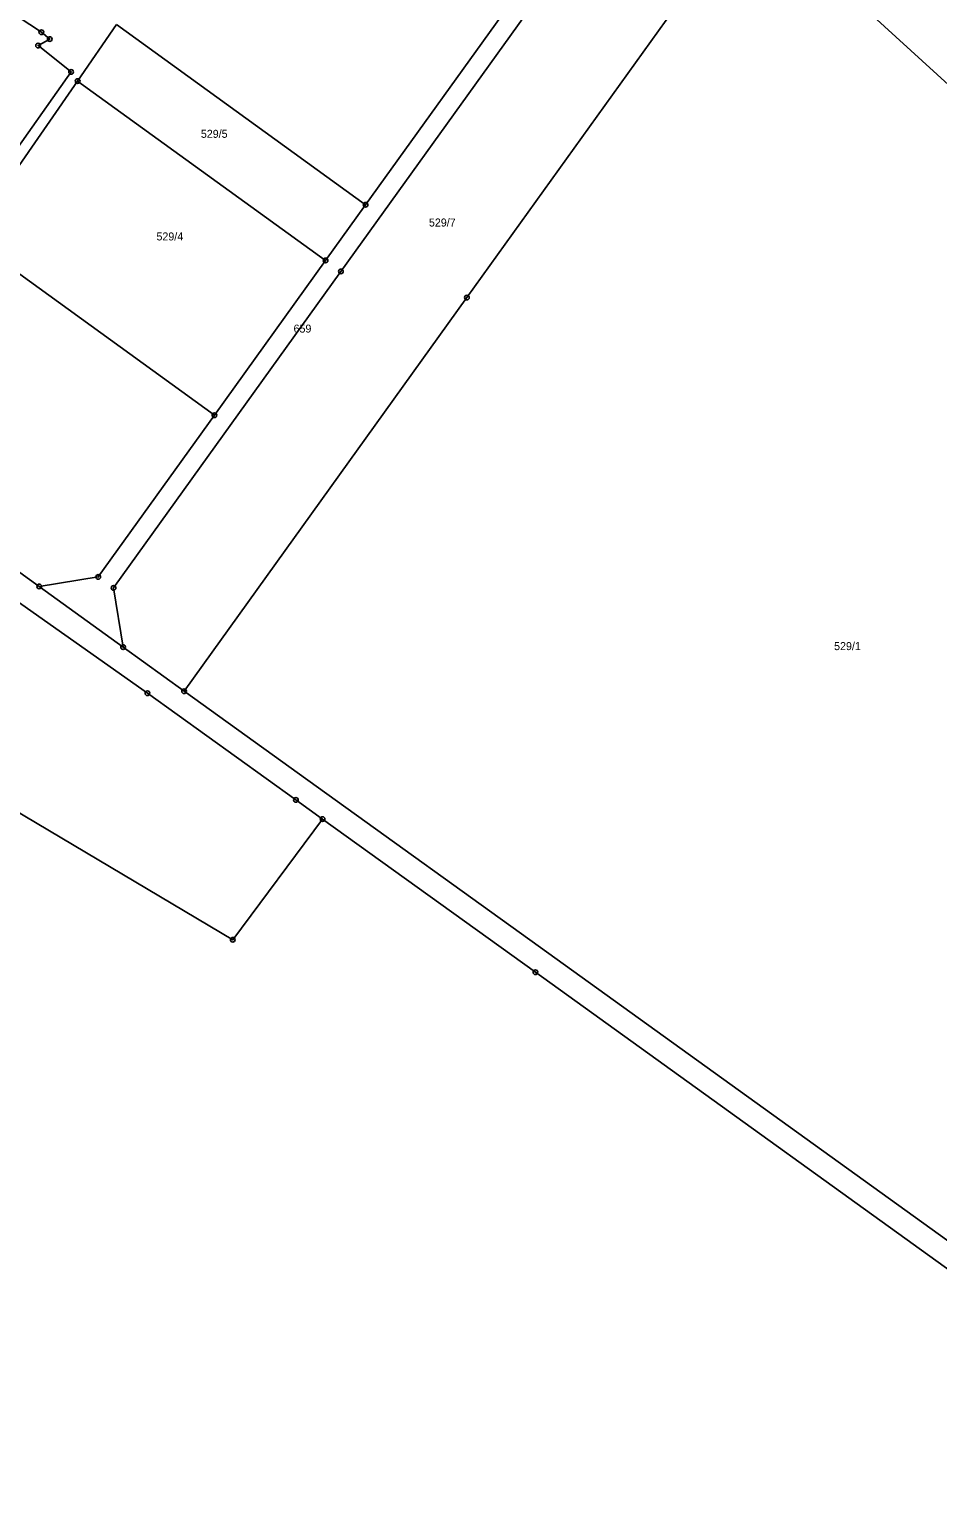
# Model space of a CAD drawing. Extents: x -758582 to -751794, y -998770 to -994350.
# Drawn here: x -753914.4 to -753721.4, y -997454.9 to -997140.7 of the extents above; entities that cross this region are included whole.
import ezdxf

# ---------------------------------------------------------------- set-up
doc = ezdxf.new("R2010")
doc.units = 0
for name, color, linetype in [('Hranice parcel', 7, 'Continuous'), ('Parcelní čísla', 7, 'Continuous'), ('Značky bodu BP', 7, 'Continuous')]:
    doc.layers.add(name, color=color, linetype=linetype)

msp = doc.modelspace()

# ---------------------------------------------------------------- linework, layer by layer
at = {"layer": 'Hranice parcel'}
for p, q in [((-753843, -997177.95), (-753781.75, -997092.75)), ((-753904.22, -997151.68), (-753895.93, -997139.69)), ((-753843, -997177.95), (-753895.93, -997139.69)), ((-753917.91, -997171.47), (-753904.22, -997151.68)), ((-753851.51, -997189.79), (-753904.22, -997151.68)), ((-753851.51, -997189.79), (-753843, -997177.95)), ((-753875.15, -997222.67), (-753927.26, -997184.99)), ((-753875.15, -997222.67), (-753851.51, -997189.79)), ((-753956.46, -997227.2), (-753912.39, -997259.05)), ((-753894.56, -997271.94), (-753912.39, -997259.05)), ((-753894.56, -997271.94), (-753881.59, -997281.3))]:
    msp.add_line(p, q, dxfattribs=at)
for points in [[(-753778.99, -997095.76), (-753848.26, -997192.12), (-753896.59, -997259.35), (-753894.56, -997271.94)], [(-753761.15, -997113.77), (-753821.47, -997197.67), (-753881.59, -997281.3)], [(-753761.15, -997113.77), (-753757.5, -997117.4), (-753719.05, -997152.45), (-753671.74, -997191.64), (-753659.01, -997201.73), (-753633.73, -997223.1), (-753599.82, -997250.03)], [(-753919.98, -997170.14), (-753905.61, -997149.74), (-753912.63, -997144.13), (-753910.16, -997142.77), (-753911.94, -997141.3), (-753916.88, -997138.01), (-753932.01, -997161.86)], [(-753852.15, -997308.47), (-753871.25, -997334.09), (-753918.09, -997306.31), (-753976.45, -997272.88), (-753996.61, -997232.71), (-754036.34, -997178.45)], [(-753912.39, -997259.05), (-753899.84, -997257.02), (-753875.15, -997222.67)], [(-753959.77, -997232.16), (-753889.38, -997281.72), (-753857.82, -997304.4), (-753852.15, -997308.47)], [(-753881.59, -997281.3), (-753855.26, -997300.22), (-753804.06, -997337.03), (-753710.64, -997404.19)], [(-753854.21, -997753.52), (-753840.93, -997729.59), (-753764.33, -997590.99), (-753741.88, -997551.71), (-753721.27, -997514.44), (-753700.33, -997475.68), (-753688.35, -997452.29), (-753682.81, -997440.16), (-753682.49, -997434.57), (-753687.49, -997427.26), (-753699.24, -997418.42), (-753806.91, -997341), (-753852.15, -997308.47)]]:
    msp.add_lwpolyline(points, dxfattribs=at)
at = {"layer": 'Značky bodu BP'}
for centre, radius in [((-753912.63, -997144.13), 0.5), ((-753911.94, -997141.3), 0.5), ((-753911.94, -997141.3), 0.0303), ((-753910.16, -997142.77), 0.5), ((-753910.16, -997142.77), 0.0303), ((-753912.63, -997144.13), 0.0303), ((-753905.61, -997149.74), 0.5), ((-753905.61, -997149.74), 0.0303), ((-753904.22, -997151.68), 0.5), ((-753904.22, -997151.68), 0.0303), ((-753843, -997177.95), 0.5), ((-753843, -997177.95), 0.0303), ((-753851.51, -997189.79), 0.5), ((-753851.51, -997189.79), 0.0303), ((-753848.26, -997192.12), 0.5), ((-753848.26, -997192.12), 0.0303), ((-753821.47, -997197.67), 0.5), ((-753821.47, -997197.67), 0.0303), ((-753875.15, -997222.67), 0.5), ((-753875.15, -997222.67), 0.0303), ((-753899.84, -997257.02), 0.5), ((-753912.39, -997259.05), 0.5), ((-753912.39, -997259.05), 0.0303), ((-753899.84, -997257.02), 0.0303), ((-753896.59, -997259.35), 0.5), ((-753896.59, -997259.35), 0.0303), ((-753894.56, -997271.94), 0.5), ((-753894.56, -997271.94), 0.0303), ((-753889.38, -997281.72), 0.5), ((-753889.38, -997281.72), 0.0303), ((-753881.59, -997281.3), 0.5), ((-753881.59, -997281.3), 0.0303), ((-753857.82, -997304.4), 0.5), ((-753857.82, -997304.4), 0.0303), ((-753852.15, -997308.47), 0.5), ((-753852.15, -997308.47), 0.0303), ((-753871.25, -997334.09), 0.5), ((-753871.25, -997334.09), 0.0303), ((-753806.91, -997341), 0.5), ((-753806.91, -997341), 0.0303)]:
    msp.add_circle(centre, radius, dxfattribs=at)

# ---------------------------------------------------------------- texts
at = {"layer": 'Parcelní čísla'}
for s, p in [('529/5', (-753878.03, -997163.74)), ('529/7', (-753829.54, -997182.58)), ('529/4', (-753887.47, -997185.54)), ('659', (-753858.32, -997205.12)), ('529/1', (-753743.4, -997272.57))]:
    msp.add_text(s, height=1.7, dxfattribs=at).set_placement(p)

doc.saveas('drawing.dxf')
